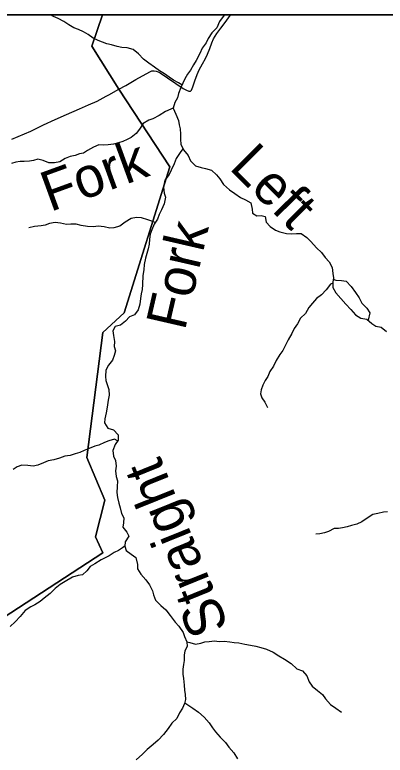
# Model space of a CAD drawing. Extents: x 0 to 34, y 0 to 22.
# Drawn here: x 6.209 to 7.083, y 19.152 to 20.9 of the extents above; entities that cross this region are included whole.
import ezdxf

# ---------------------------------------------------------------- set-up
doc = ezdxf.new("R2010")
doc.units = 0
for name, color, linetype in [('Default', 7, 'Continuous'), ('GM_X_County_Road', 7, 'Continuous'), ('GM_X_Minor_River', 7, 'Continuous'), ('GM_X_Minor_River_Text', 7, 'Continuous'), ('SH_Cut_Line', 7, 'Continuous'), ('SH_Data', 7, 'Continuous')]:
    doc.layers.add(name, color=color, linetype=linetype)

msp = doc.modelspace()

# ---------------------------------------------------------------- linework, layer by layer
at = {"layer": 'Default'}
for points in [[(6.1627, 19.4643), (6.4166, 19.6301), (6.3989, 19.6679), (6.4211, 19.7542), (6.3788, 19.8553), (6.4168, 20.1498), (6.467, 20.1963), (6.5744, 20.5412), (6.4542, 20.7247), (6.3907, 20.8258), (6.416, 20.9), (2.4845, 20.9)], [(8.9, 18.9397), (8.9, 20.9), (6.416, 20.9), (6.3907, 20.8258), (6.4542, 20.7247), (6.5744, 20.5412), (6.467, 20.1963), (6.4168, 20.1498), (6.3788, 19.8553), (6.4211, 19.7542), (6.3989, 19.6679), (6.4166, 19.6301), (6.1627, 19.4643), (5.935, 19.2098), (5.9881, 19.1818), (6.0158, 19.1833), (6.0473, 19.1917), (6.082, 19.1783), (6.0902, 19.1718), (6.104, 19.1492)]]:
    msp.add_lwpolyline(points, dxfattribs=at)
at = {"layer": 'GM_X_County_Road'}
for points in [[(6.6258, 20.7222), (6.6286, 20.7303), (6.6336, 20.7443), (6.6392, 20.7591), (6.6438, 20.77), (6.6515, 20.784), (6.6586, 20.7972), (6.6634, 20.8069), (6.6687, 20.8206), (6.6733, 20.8336), (6.6776, 20.8432), (6.6853, 20.8557), (6.6947, 20.8684), (6.7054, 20.8819), (6.7168, 20.8987), (6.7179, 20.9)], [(6.4248, 20.7076), (6.431, 20.7107), (6.4544, 20.7242), (6.4707, 20.7333), (6.4946, 20.7473), (6.5271, 20.7654), (6.5319, 20.7675), (6.5373, 20.768), (6.5421, 20.7672), (6.5469, 20.7657), (6.552, 20.7631), (6.6059, 20.7263), (6.6143, 20.7219), (6.6192, 20.7201), (6.6232, 20.7199), (6.6258, 20.7222)], [(6.2018, 20.6062), (6.2468, 20.6255), (6.2763, 20.64), (6.3043, 20.653), (6.3305, 20.665), (6.3613, 20.6782), (6.3831, 20.6876), (6.403, 20.6962), (6.4248, 20.7076)]]:
    msp.add_lwpolyline(points, dxfattribs=at)
at = {"layer": 'GM_X_Minor_River'}
for points in [[(6.6029, 20.7344), (6.5947, 20.7395), (6.583, 20.7457), (6.5732, 20.7529), (6.5619, 20.7606), (6.5506, 20.7676), (6.5386, 20.7764), (6.525, 20.7856), (6.5126, 20.7956), (6.5006, 20.8082), (6.4882, 20.8178), (6.4742, 20.8217), (6.4617, 20.8229), (6.4504, 20.8253), (6.4372, 20.8288), (6.4262, 20.8312), (6.4156, 20.8351), (6.4054, 20.8393), (6.3938, 20.8451), (6.3817, 20.8535), (6.3708, 20.8597), (6.3595, 20.8651), (6.3485, 20.8694), (6.3365, 20.8767), (6.3248, 20.884), (6.3112, 20.8913), (6.3003, 20.896), (6.293, 20.9)], [(6.703, 20.9), (6.7028, 20.8995), (6.6921, 20.8844), (6.6855, 20.8696), (6.6733, 20.8576), (6.6648, 20.8444), (6.6602, 20.8342), (6.6506, 20.821), (6.6452, 20.8089), (6.6371, 20.7923), (6.6302, 20.7817), (6.6237, 20.7696), (6.6164, 20.7598), (6.6099, 20.7492), (6.6049, 20.739), (6.6003, 20.7281), (6.5948, 20.7145), (6.5925, 20.7042), (6.5867, 20.6929), (6.5828, 20.6797), (6.5887, 20.6656), (6.5947, 20.6503), (6.5965, 20.6405), (6.5987, 20.631), (6.5997, 20.6181), (6.6, 20.6059), (6.6003, 20.5945), (6.6066, 20.5812), (6.6182, 20.5678), (6.6234, 20.5553), (6.635, 20.5438), (6.6486, 20.5395), (6.6588, 20.5371), (6.6732, 20.5332), (6.6845, 20.5225), (6.6927, 20.5126), (6.7009, 20.4992), (6.7152, 20.487), (6.728, 20.4785), (6.7412, 20.4689), (6.7533, 20.4631), (6.7653, 20.4558), (6.769, 20.441), (6.7693, 20.4315), (6.7802, 20.4257), (6.7897, 20.4264), (6.7995, 20.4241), (6.802, 20.4104), (6.8114, 20.4001)], [(6.5831, 20.6806), (6.5767, 20.6774), (6.5646, 20.6718), (6.5493, 20.6625), (6.5349, 20.6542), (6.525, 20.6513), (6.5117, 20.6431), (6.5033, 20.6302), (6.4952, 20.6197), (6.4834, 20.6103), (6.4739, 20.6054), (6.464, 20.601), (6.4534, 20.598), (6.4416, 20.5947), (6.4295, 20.5933), (6.4178, 20.5926), (6.4075, 20.5927), (6.3942, 20.5875), (6.3805, 20.5796), (6.371, 20.5733), (6.3612, 20.5715), (6.3517, 20.5681), (6.3395, 20.5652), (6.3274, 20.5607), (6.3148, 20.5529), (6.3023, 20.5503), (6.2894, 20.5504), (6.2758, 20.5562), (6.263, 20.5594), (6.2527, 20.5564), (6.2433, 20.5546), (6.2311, 20.5539), (6.2213, 20.5536), (6.2111, 20.5518), (6.2012, 20.5493)], [(6.6054, 20.5836), (6.599, 20.5752), (6.5894, 20.5609), (6.5851, 20.548), (6.5778, 20.5333), (6.5728, 20.5227), (6.5628, 20.5099), (6.56, 20.4932), (6.5614, 20.4788), (6.564, 20.4692), (6.5612, 20.4541), (6.5547, 20.4394), (6.5496, 20.4288), (6.5454, 20.4178), (6.5377, 20.4057), (6.5323, 20.3925), (6.528, 20.3819), (6.5264, 20.3702), (6.526, 20.3588), (6.5232, 20.3478), (6.5201, 20.3364), (6.517, 20.3255), (6.5142, 20.3103), (6.5133, 20.2978), (6.5106, 20.2845), (6.5104, 20.2633), (6.5092, 20.2512), (6.5068, 20.2413), (6.5056, 20.23), (6.5036, 20.2171), (6.4997, 20.2034), (6.4909, 20.1921), (6.4795, 20.1869), (6.4703, 20.1768), (6.4585, 20.1674), (6.4459, 20.1641), (6.4402, 20.1539), (6.4416, 20.1428), (6.4441, 20.1288), (6.4437, 20.1166), (6.4462, 20.1071), (6.4431, 20.0958), (6.4392, 20.0844), (6.4297, 20.0728), (6.4239, 20.061), (6.423, 20.0459), (6.424, 20.0364), (6.4266, 20.0269), (6.4311, 20.0155), (6.4317, 20.0022), (6.4293, 19.99), (6.4269, 19.9741), (6.4245, 19.9601), (6.4214, 19.9461), (6.4202, 19.9366), (6.428, 19.9244), (6.4416, 19.9205), (6.4529, 19.9087), (6.4524, 19.8958), (6.4459, 19.8856), (6.4405, 19.8716), (6.4419, 19.8579), (6.4467, 19.848), (6.4481, 19.8347), (6.4465, 19.8237), (6.4483, 19.8097), (6.4508, 19.8002), (6.4503, 19.7858), (6.4498, 19.7725), (6.4513, 19.7603), (6.4546, 19.7474), (6.4575, 19.736), (6.4608, 19.7231), (6.466, 19.7124), (6.4651, 19.7007), (6.4639, 19.6908), (6.4729, 19.679), (6.4781, 19.6694), (6.4693, 19.6559), (6.4688, 19.6456), (6.4714, 19.6353), (6.4835, 19.6269), (6.4947, 19.6185), (6.4984, 19.6025), (6.4983, 19.5923), (6.5065, 19.5797), (6.5178, 19.5659), (6.5264, 19.5541), (6.5335, 19.5404), (6.5364, 19.5309), (6.5409, 19.5183), (6.5532, 19.5057), (6.5649, 19.4953), (6.5754, 19.4816), (6.587, 19.4659), (6.596, 19.4564), (6.6057, 19.4419), (6.609, 19.4324), (6.615, 19.4194), (6.6157, 19.4088), (6.6099, 19.3986)], [(6.5403, 20.4098), (6.5325, 20.413), (6.5227, 20.4157), (6.5076, 20.4208), (6.4958, 20.4216), (6.4837, 20.4191), (6.4696, 20.4108), (6.457, 20.4011), (6.4426, 20.3974), (6.4328, 20.3967), (6.4199, 20.3991), (6.4052, 20.4008), (6.3942, 20.3997), (6.3802, 20.4002), (6.3658, 20.4026), (6.3537, 20.4057), (6.3408, 20.4058), (6.331, 20.4052), (6.317, 20.4083), (6.3038, 20.4099), (6.2909, 20.4074), (6.2806, 20.4033), (6.2711, 20.4015), (6.2556, 20.4001), (6.2423, 20.3972)], [(6.8114, 20.4001), (6.8238, 20.3912), (6.8344, 20.3877), (6.8499, 20.3838), (6.8612, 20.3826), (6.8734, 20.384), (6.8847, 20.3835), (6.8975, 20.3739), (6.9073, 20.3647), (6.9208, 20.3502), (6.9321, 20.3387), (6.941, 20.3273), (6.9508, 20.3166), (6.9575, 20.3033), (6.9593, 20.2892), (6.9603, 20.2789), (6.9587, 20.2691), (6.959, 20.2562), (6.9661, 20.244), (6.9777, 20.2299), (6.9897, 20.2169), (7.0013, 20.2046), (7.0122, 20.192), (7.0254, 20.1839), (7.0394, 20.1816), (7.051, 20.1716), (7.0608, 20.1647), (7.0733, 20.1623), (7.0853, 20.152)], [(6.9599, 20.2762), (6.9663, 20.2736), (6.9792, 20.2727), (6.9902, 20.2715), (7.0022, 20.2585), (7.0123, 20.2448), (7.0209, 20.2318), (7.0276, 20.2196), (7.0389, 20.2077), (7.0463, 20.1963), (7.0424, 20.179)], [(6.9588, 20.2661), (6.9534, 20.2642), (6.9434, 20.2506), (6.932, 20.2393), (6.9209, 20.23), (6.911, 20.2194), (6.9026, 20.2089), (6.8949, 20.1949), (6.883, 20.1836), (6.8754, 20.1708), (6.8677, 20.1598), (6.8623, 20.1477), (6.8538, 20.133), (6.8473, 20.1198), (6.8408, 20.1077), (6.8339, 20.0979), (6.8258, 20.0843), (6.8189, 20.0703), (6.8108, 20.0579), (6.8054, 20.0465), (6.7996, 20.0367), (6.7939, 20.0257), (6.7904, 20.0148), (6.7888, 20.0049), (6.7913, 19.9954), (6.7988, 19.9859), (6.8048, 19.9729)], [(6.4515, 19.8943), (6.4441, 19.8985), (6.4304, 19.8944), (6.4209, 19.8907), (6.4069, 19.884), (6.3974, 19.8814), (6.3841, 19.8762), (6.3727, 19.8714), (6.3624, 19.8669), (6.351, 19.8636), (6.3396, 19.8599), (6.3271, 19.8577), (6.3142, 19.8533), (6.3009, 19.8492), (6.2877, 19.8467), (6.2763, 19.8422), (6.263, 19.8366), (6.2524, 19.8344), (6.2399, 19.8361), (6.2259, 19.8369), (6.2148, 19.8325), (6.2053, 19.8269)], [(7.0882, 19.727), (7.0783, 19.7256), (7.0655, 19.723), (7.0537, 19.7205), (7.0404, 19.7119), (7.0278, 19.7029), (7.0153, 19.6977), (7.0031, 19.6947), (6.9929, 19.6914), (6.9822, 19.6892), (6.9724, 19.6874), (6.9622, 19.6871), (6.9492, 19.68), (6.9397, 19.6774), (6.9287, 19.6748), (6.9193, 19.6738)], [(6.4689, 19.646), (6.4631, 19.6415), (6.4532, 19.6351), (6.4437, 19.6306), (6.4315, 19.6224), (6.4221, 19.6183), (6.4125, 19.6131), (6.3977, 19.6041), (6.387, 19.5973), (6.3786, 19.5872), (6.3683, 19.5781), (6.3581, 19.5763), (6.3452, 19.5723), (6.3277, 19.5622), (6.3159, 19.5554), (6.3044, 19.546), (6.2922, 19.534), (6.2781, 19.5231), (6.2686, 19.5152), (6.256, 19.507), (6.2465, 19.5021), (6.2336, 19.4939), (6.2214, 19.4796), (6.2095, 19.4668), (6.1977, 19.4563)], [(6.615, 19.4194), (6.6218, 19.4179), (6.635, 19.4143), (6.6479, 19.4169), (6.6574, 19.4195), (6.6676, 19.4209), (6.6798, 19.4219), (6.6907, 19.4207), (6.7025, 19.421), (6.7161, 19.4201), (6.7263, 19.4185), (6.7377, 19.4177), (6.7516, 19.4145), (6.7649, 19.4121), (6.7773, 19.4094), (6.7894, 19.4062), (6.803, 19.4027), (6.8181, 19.395), (6.832, 19.3865), (6.8452, 19.3785), (6.8607, 19.3688), (6.8738, 19.3562), (6.8878, 19.3516), (6.8979, 19.3397), (6.9031, 19.3252), (6.9106, 19.3149), (6.9226, 19.305), (6.9346, 19.2954), (6.9421, 19.2855), (6.9538, 19.2721), (6.9662, 19.2629), (6.9794, 19.2541)], [(6.6099, 19.3986), (6.6087, 19.388), (6.6082, 19.3755), (6.6066, 19.366), (6.6054, 19.355), (6.6056, 19.3436), (6.6067, 19.333), (6.6081, 19.3178), (6.6091, 19.306), (6.6105, 19.2958), (6.6116, 19.284), (6.6092, 19.2738), (6.6042, 19.2628), (6.5977, 19.2523), (6.5908, 19.239), (6.5797, 19.2281), (6.5709, 19.2149), (6.5598, 19.201), (6.5468, 19.1878), (6.535, 19.1776), (6.5212, 19.1656), (6.5102, 19.1543), (6.4953, 19.1408)], [(6.6096, 19.2756), (6.6172, 19.2707), (6.6292, 19.2634), (6.642, 19.2538), (6.6552, 19.2419), (6.6672, 19.2289), (6.6754, 19.2167), (6.6821, 19.2072), (6.6934, 19.1949), (6.7061, 19.1819), (6.7136, 19.1709), (6.7252, 19.1579), (6.7346, 19.1438)]]:
    msp.add_lwpolyline(points, dxfattribs=at)
at = {"layer": 'SH_Cut_Line'}
msp.add_lwpolyline([(2.4352, 14.1), (8.9, 14.1), (8.9, 20.9), (2.4845, 20.9), (2.4809, 20.6393), (2.4757, 20.2566), (2.4573, 18.9074), (2.4581, 18.1825), (2.4581, 18.1772), (2.4586, 17.7785), (2.4545, 17.2795), (2.4313, 15.0183), (2.4372, 14.2719)], close=True, dxfattribs=at)
at = {"layer": 'SH_Data'}
msp.add_line((2.1, 20.9), (8.9, 20.9), dxfattribs=at)

# ---------------------------------------------------------------- texts
at = {"layer": 'GM_X_Minor_River_Text'}
for s, rotation, p in [('Fork', 20.0008, (6.2924, 20.4342)), ('Left', 315.0017, (6.7124, 20.5377)), ('Fork', 77.0003, (6.6099, 20.1525)), ('Straight', 112.0011, (6.7144, 19.4549))]:
    msp.add_text(s, height=0.0947, rotation=rotation, dxfattribs=at).set_placement(p)

doc.saveas('drawing.dxf')
